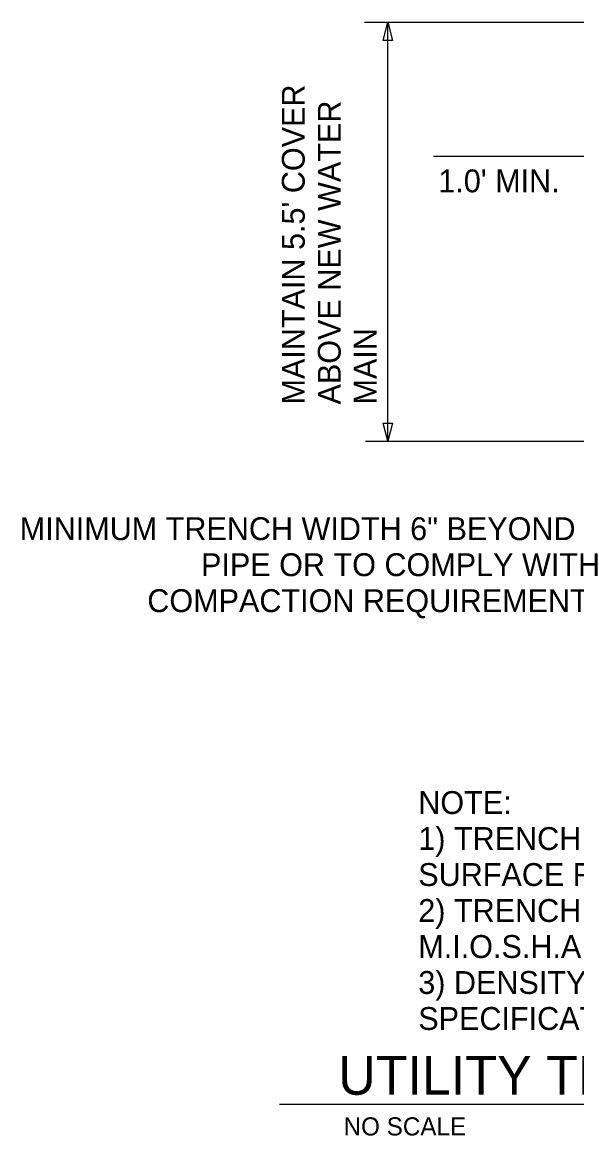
# Model space of a CAD drawing. Extents: x 9937.2 to 10006.2, y 10008.4 to 10068.3.
# Drawn here: x 9937.2 to 9962.5, y 10009.3 to 10060.2 of the extents above; entities that cross this region are included whole.
import ezdxf

# ---------------------------------------------------------------- set-up
doc = ezdxf.new("R2010")
doc.units = 0
for name, color, linetype in [('Default', 7, 'Continuous'), ('G-ANNO-TEXT', 7, 'Continuous'), ('G-ANNO-TTXT', 7, 'Continuous')]:
    doc.layers.add(name, color=color, linetype=linetype)

# ---------------------------------------------------------------- blocks, each defined once
blk = doc.blocks.new('TERARR')
at = {"layer": 'Default'}
blk.add_lwpolyline([(-0.667, 0.167), (0, 0), (-0.667, -0.167)], close=True, dxfattribs=at)

msp = doc.modelspace()

# ---------------------------------------------------------------- linework, layer by layer
at = {"layer": 'G-ANNO-TEXT'}
for p, q in [((9952.779, 10060.199), (9963.277, 10060.199)), ((9953.851, 10041.058), (9953.851, 10060.194)), ((9963.435, 10054.071), (9955.939, 10054.071)), ((9952.831, 10041.058), (9970.536, 10041.058)), ((9948.906, 10010.783), (10002.152, 10010.783))]:
    msp.add_line(p, q, dxfattribs=at)

# ---------------------------------------------------------------- block references
at = {"layer": 'G-ANNO-TEXT', "xscale": 1.25, "yscale": 1.25}
for p, rotation in [((9953.851, 10060.199), 90), ((9953.851, 10041.058), -90)]:
    msp.add_blockref('TERARR', p, dxfattribs=dict(at, rotation=rotation))

# ---------------------------------------------------------------- texts
at = {"layer": 'G-ANNO-TEXT'}
for s, p in [("MAINTAIN 5.5' COVER", (9950.055, 10042.738)), ('ABOVE NEW WATER ', (9951.699, 10042.738)), ('MAIN', (9953.343, 10042.738))]:
    msp.add_text(s, height=1.044, rotation=90, dxfattribs=at).set_placement(p)
for s, height, p in [("1.0' MIN.", 1.044, (9956.159, 10052.431)), ('MINIMUM TRENCH WIDTH 6" BEYOND', 1.044, (9937.037, 10036.544)), (' PIPE OR TO COMPLY WITH', 1.044, (9944.932, 10034.9)), (' COMPACTION REQUIREMENTS', 1.044, (9942.476, 10033.256)), ('NOTE:', 1.044, (9955.243, 10024.034)), ('1) TRENCH DETAILS SHOW TYPE OF BACKFILL AND ', 1.044, (9955.243, 10022.39)), ('SURFACE RESTORATION ONLY.', 1.044, (9955.243, 10020.746)), ('2) TRENCHING TO CONFORM TO ALL APPLICABLE ', 1.044, (9955.243, 10019.102)), ('M.I.O.S.H.A. STANDARDS.', 1.044, (9955.243, 10017.458)), ('3) DENSITY TESTING PER UNIVERSITY OF MICHIGAN ', 1.044, (9955.243, 10015.814)), ('SPECIFICATIONS.', 1.044, (9955.243, 10014.17)), ('NO SCALE', 0.828, (9951.831, 10009.349))]:
    msp.add_text(s, height=height, dxfattribs=at).set_placement(p)
at = {"layer": 'G-ANNO-TTXT'}
msp.add_text('UTILITY TRENCH WITH ASPHALT PATCH', height=1.776, dxfattribs=at).set_placement((9951.584, 10011.21))

doc.saveas('drawing.dxf')
